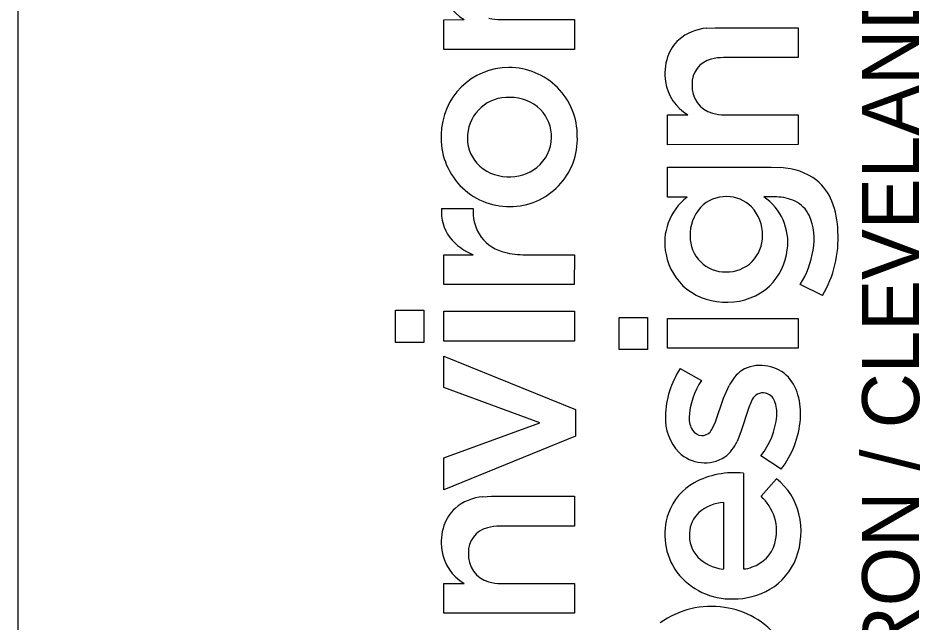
# Model space of a CAD drawing. Extents: x 0 to 34, y 0 to 22.
# Drawn here: x 32 to 32.901, y 2.778 to 3.382 of the extents above; entities that cross this region are included whole.
import ezdxf

# ---------------------------------------------------------------- set-up
doc = ezdxf.new("R2010")
doc.units = 0
doc.layers.add('SH_Border', color=7, linetype='Continuous')
doc.layers.add('SH_Data', color=7, linetype='Continuous')

msp = doc.modelspace()

# ---------------------------------------------------------------- linework, layer by layer
at = {"layer": 'SH_Border'}
msp.add_line((32, 0.5), (32, 21.5), dxfattribs=at)
at = {"layer": 'SH_Data'}
for p, q in [((32.42542, 3.38066), (32.44552, 3.38071)), ((32.42542, 3.35086), (32.42542, 3.38066)), ((32.48222, 3.38071), (32.55569, 3.38071)), ((32.55569, 3.38071), (32.55571, 3.35096)), ((32.68784, 3.3722), (32.69634, 3.37266)), ((32.69634, 3.37266), (32.77916, 3.37266)), ((32.77916, 3.37266), (32.77917, 3.34287)), ((32.55571, 3.35096), (32.42542, 3.35086)), ((32.77917, 3.34287), (32.70485, 3.3428)), ((32.64888, 3.2855), (32.66897, 3.28555)), ((32.64888, 3.25569), (32.64888, 3.2855)), ((32.70568, 3.28555), (32.77915, 3.28555)), ((32.77915, 3.28555), (32.77917, 3.25579)), ((32.77917, 3.25579), (32.64888, 3.25569)), ((32.6489, 3.20336), (32.64889, 3.23322)), ((32.64889, 3.23322), (32.75236, 3.23322)), ((32.75236, 3.23322), (32.76191, 3.23285)), ((32.66836, 3.20336), (32.6489, 3.20336)), ((32.75763, 3.20356), (32.74487, 3.20361)), ((32.42299, 3.19193), (32.45454, 3.19193)), ((32.42542, 3.14577), (32.45473, 3.14579)), ((32.42542, 3.11593), (32.42542, 3.14577)), ((32.50413, 3.14581), (32.55571, 3.14573)), ((32.55571, 3.14573), (32.55565, 3.11593)), ((32.55565, 3.11593), (32.42542, 3.11593)), ((32.8036, 3.10491), (32.7812, 3.11598)), ((32.37705, 3.05818), (32.37705, 3.09026)), ((32.37705, 3.09026), (32.40543, 3.09026)), ((32.40543, 3.09026), (32.40543, 3.05818)), ((32.42542, 3.05942), (32.42542, 3.08928)), ((32.42542, 3.08928), (32.55571, 3.08928)), ((32.55571, 3.08928), (32.55571, 3.05942)), ((32.60051, 3.05111), (32.60051, 3.08319)), ((32.60051, 3.08319), (32.62889, 3.08319)), ((32.62889, 3.08319), (32.62889, 3.05111)), ((32.64888, 3.05234), (32.64888, 3.0822)), ((32.64888, 3.0822), (32.77917, 3.0822)), ((32.77917, 3.0822), (32.77917, 3.05234)), ((32.40543, 3.05818), (32.37705, 3.05818)), ((32.55571, 3.05942), (32.42542, 3.05942)), ((32.62889, 3.05111), (32.60051, 3.05111)), ((32.77917, 3.05234), (32.64888, 3.05234)), ((32.42542, 3.01327), (32.42542, 3.0446)), ((32.42542, 3.0446), (32.5567, 2.9913)), ((32.66151, 3.03207), (32.68268, 3.02025)), ((32.52117, 2.97798), (32.42542, 3.01327)), ((32.70483, 3.00258), (32.71036, 3.01526)), ((32.69675, 2.97868), (32.70483, 3.00258)), ((32.73342, 3.00101), (32.72985, 2.9933)), ((32.5567, 2.9913), (32.5567, 2.96441)), ((32.72985, 2.9933), (32.72213, 2.96882)), ((32.42542, 2.94294), (32.52117, 2.97798)), ((32.69299, 2.97117), (32.69675, 2.97868)), ((32.5567, 2.96441), (32.42542, 2.91086)), ((32.72213, 2.96882), (32.71822, 2.95921)), ((32.42542, 2.91086), (32.42542, 2.94294)), ((32.76214, 2.93141), (32.74198, 2.94469)), ((32.72453, 2.92747), (32.72463, 2.83195)), ((32.74228, 2.90465), (32.75768, 2.922)), ((32.46439, 2.90397), (32.47289, 2.90443)), ((32.47289, 2.90443), (32.55571, 2.90443)), ((32.55571, 2.90443), (32.55571, 2.87465)), ((32.70489, 2.83182), (32.70489, 2.89834)), ((32.55571, 2.87465), (32.4814, 2.87457)), ((32.70361, 2.83165), (32.70489, 2.83182)), ((32.42542, 2.81728), (32.44552, 2.81733)), ((32.42542, 2.78747), (32.42542, 2.81728)), ((32.48222, 2.81733), (32.55569, 2.81733)), ((32.55569, 2.81733), (32.55571, 2.78756)), ((32.55571, 2.78756), (32.42542, 2.78747))]:
    msp.add_line(p, q, dxfattribs=at)
for points in [[(32.42542, 3.35086), (32.42542, 3.38066), (32.44552, 3.38071)], [(32.48222, 3.38071), (32.55569, 3.38071), (32.55571, 3.35096), (32.42542, 3.35086)], [(32.68784, 3.3722), (32.69634, 3.37266), (32.77916, 3.37266), (32.77917, 3.34287), (32.70485, 3.3428)], [(32.64888, 3.25569), (32.64888, 3.2855), (32.66897, 3.28555)], [(32.70568, 3.28555), (32.77915, 3.28555), (32.77917, 3.25579), (32.64888, 3.25569)], [(32.66836, 3.20336), (32.6489, 3.20336), (32.64889, 3.23322), (32.75236, 3.23322), (32.76191, 3.23285)], [(32.75763, 3.20356), (32.74487, 3.20361)], [(32.42299, 3.19193), (32.45454, 3.19193)], [(32.50413, 3.14581), (32.55571, 3.14573), (32.55565, 3.11593), (32.42542, 3.11593)], [(32.42542, 3.11593), (32.42542, 3.14577), (32.45473, 3.14579)], [(32.8036, 3.10491), (32.7812, 3.11598)], [(32.66151, 3.03207), (32.68268, 3.02025)], [(32.69299, 2.97117), (32.69675, 2.97868), (32.70483, 3.00258), (32.71036, 3.01526)], [(32.73342, 3.00101), (32.72985, 2.9933), (32.72213, 2.96882), (32.71822, 2.95921)], [(32.76214, 2.93141), (32.74198, 2.94469)], [(32.72453, 2.92747), (32.72463, 2.83195)], [(32.74228, 2.90465), (32.75768, 2.922)], [(32.46439, 2.90397), (32.47289, 2.90443), (32.55571, 2.90443), (32.55571, 2.87465), (32.4814, 2.87457)], [(32.70361, 2.83165), (32.70489, 2.83182), (32.70489, 2.89834)], [(32.42542, 2.78747), (32.42542, 2.81728), (32.44552, 2.81733)], [(32.48222, 2.81733), (32.55569, 2.81733), (32.55571, 2.78756), (32.42542, 2.78747)]]:
    msp.add_lwpolyline(points, dxfattribs=at)
for points in [[(32.37705, 3.05818), (32.37705, 3.09026), (32.40543, 3.09026), (32.40543, 3.05818)], [(32.42542, 3.05942), (32.42542, 3.08928), (32.55571, 3.08928), (32.55571, 3.05942)], [(32.60051, 3.05111), (32.60051, 3.08319), (32.62889, 3.08319), (32.62889, 3.05111)], [(32.64888, 3.05234), (32.64888, 3.0822), (32.77917, 3.0822), (32.77917, 3.05234)], [(32.42542, 2.91086), (32.42542, 2.94294), (32.52117, 2.97798), (32.42542, 3.01327), (32.42542, 3.0446), (32.5567, 2.9913), (32.5567, 2.96441)]]:
    msp.add_lwpolyline(points, close=True, dxfattribs=at)
for centre, radius, start, end in [((32.47027, 3.42141), 0.04763, 188.96462, 238.69865), ((32.47027, 3.42141), 0.04763, 188.96462, 238.69865), ((32.48183, 3.42286), 0.04215, 254.08913, 270.52838), ((32.48183, 3.42286), 0.04215, 254.08913, 270.52838), ((32.69216, 3.32251), 0.04988, 94.97056, 130.22484), ((32.69216, 3.32251), 0.04988, 94.97056, 130.22484), ((32.68694, 3.33085), 0.04016, 132.22383, 161.68229), ((32.68694, 3.33085), 0.04016, 132.22383, 161.68229), ((32.70217, 3.32642), 0.05602, 162.27398, 187.79173), ((32.70217, 3.32642), 0.05602, 162.27398, 187.79173), ((32.70453, 3.29679), 0.04601, 89.60515, 105.33026), ((32.70453, 3.29679), 0.04601, 89.60515, 105.33026), ((32.69828, 3.31689), 0.02498, 103.68683, 182.21395), ((32.69828, 3.31689), 0.02498, 103.68683, 182.21395), ((32.49014, 3.26543), 0.0674, 89.84756, 179.64047), ((32.49014, 3.26543), 0.0674, 89.84756, 179.64047), ((32.49057, 3.26474), 0.0681, 359.54009, 90.21138), ((32.49057, 3.26474), 0.0681, 359.54009, 90.21138), ((32.69372, 3.32624), 0.04763, 188.96462, 238.69865), ((32.69372, 3.32624), 0.04763, 188.96462, 238.69865), ((32.7008, 3.31381), 0.02757, 175.58441, 255.13816), ((32.7008, 3.31381), 0.02757, 175.58441, 255.13816), ((32.48923, 3.26263), 0.0404, 87.04809, 175.57259), ((32.48923, 3.26263), 0.0404, 87.04809, 175.57259), ((32.49204, 3.25999), 0.04299, 45.84264, 90.98008), ((32.49204, 3.25999), 0.04299, 45.84264, 90.98008), ((32.49458, 3.26421), 0.03821, 357.88569, 44.15902), ((32.49458, 3.26421), 0.03821, 357.88569, 44.15902), ((32.70529, 3.32769), 0.04215, 254.08913, 270.52838), ((32.70529, 3.32769), 0.04215, 254.08913, 270.52838), ((32.49083, 3.26209), 0.06819, 176.8344, 270.40384), ((32.49083, 3.26209), 0.06819, 176.8344, 270.40384), ((32.48729, 3.2625), 0.03848, 175.15378, 221.14706), ((32.48729, 3.2625), 0.03848, 175.15378, 221.14706), ((32.49123, 3.26139), 0.06749, 270.06243, 2.37759), ((32.49123, 3.26139), 0.06749, 270.06243, 2.37759), ((32.49446, 3.26318), 0.0383, 308.28936, 359.43468), ((32.49446, 3.26318), 0.0383, 308.28936, 359.43468), ((32.48919, 3.26607), 0.04228, 223.09994, 268.80895), ((32.48919, 3.26607), 0.04228, 223.09994, 268.80895), ((32.49096, 3.2679), 0.04418, 266.56515, 308.06078), ((32.49096, 3.2679), 0.04418, 266.56515, 308.06078), ((32.75907, 3.16789), 0.06503, 53.40344, 87.49062), ((32.75907, 3.16789), 0.06503, 53.40344, 87.49062), ((32.76517, 3.18039), 0.05141, 21.60748, 50.5577), ((32.76517, 3.18039), 0.05141, 21.60748, 50.5577), ((32.70292, 3.15813), 0.05692, 127.37482, 192.22468), ((32.70292, 3.15813), 0.05692, 127.37482, 192.22468), ((32.70693, 3.16927), 0.0346, 88.47302, 136.42562), ((32.70693, 3.16927), 0.0346, 88.47302, 136.42562), ((32.70814, 3.16963), 0.03424, 44.27195, 90.47623), ((32.70814, 3.16963), 0.03424, 44.27195, 90.47623), ((32.71421, 3.15829), 0.05472, 352.1125, 55.92295), ((32.71421, 3.15829), 0.05472, 352.1125, 55.92295), ((32.75666, 3.15725), 0.04633, 65.01687, 88.8011), ((32.75666, 3.15725), 0.04633, 65.01687, 88.8011), ((32.7626, 3.17155), 0.03085, 26.26808, 63.80301), ((32.7626, 3.17155), 0.03085, 26.26808, 63.80301), ((32.73069, 3.16714), 0.08835, 1.15143, 21.3627), ((32.73069, 3.16714), 0.08835, 1.15143, 21.3627), ((32.46616, 3.18882), 0.04329, 175.87313, 216.34747), ((32.46616, 3.18882), 0.04329, 175.87313, 216.34747), ((32.50087, 3.18948), 0.04639, 176.9688, 209.60636), ((32.50087, 3.18948), 0.04639, 176.9688, 209.60636), ((32.71141, 3.16602), 0.0401, 137.46739, 182.33237), ((32.71141, 3.16602), 0.0401, 137.46739, 182.33237), ((32.70368, 3.166), 0.03996, 358.57141, 43.53765), ((32.70368, 3.166), 0.03996, 358.57141, 43.53765), ((32.73565, 3.16154), 0.05953, 349.30734, 23.43071), ((32.73565, 3.16154), 0.05953, 349.30734, 23.43071), ((32.47466, 3.19716), 0.05511, 218.09809, 248.7907), ((32.47466, 3.19716), 0.05511, 218.09809, 248.7907), ((32.49514, 3.18814), 0.04079, 211.94466, 253.2028), ((32.49514, 3.18814), 0.04079, 211.94466, 253.2028), ((32.70645, 3.1637), 0.03511, 178.88208, 271.08374), ((32.70645, 3.1637), 0.03511, 178.88208, 271.08374), ((32.70818, 3.16404), 0.03546, 268.27882, 1.55016), ((32.70818, 3.16404), 0.03546, 268.27882, 1.55016), ((32.70538, 3.16244), 0.11383, 329.6388, 3.25998), ((32.70538, 3.16244), 0.11383, 329.6388, 3.25998), ((32.50465, 3.2165), 0.07069, 252.46555, 269.57296), ((32.50465, 3.2165), 0.07069, 252.46555, 269.57296), ((32.70463, 3.15696), 0.05837, 190.75182, 231.28919), ((32.70463, 3.15696), 0.05837, 190.75182, 231.28919), ((32.70988, 3.15708), 0.05887, 313.74196, 353.8554), ((32.70988, 3.15708), 0.05887, 313.74196, 353.8554), ((32.70738, 3.16334), 0.08771, 327.31495, 351.57478), ((32.70738, 3.16334), 0.08771, 327.31495, 351.57478), ((32.70632, 3.16112), 0.06269, 232.46061, 272.59022), ((32.70632, 3.16112), 0.06269, 232.46061, 272.59022), ((32.70954, 3.15901), 0.06051, 269.6361, 312.70877), ((32.70954, 3.15901), 0.06051, 269.6361, 312.70877), ((32.73636, 2.98258), 0.08973, 146.53104, 178.7571), ((32.73636, 2.98258), 0.08973, 146.53104, 178.7571), ((32.74661, 2.99713), 0.04053, 125.51182, 153.41595), ((32.74661, 2.99713), 0.04053, 125.51182, 153.41595), ((32.7406, 3.0026), 0.03263, 80.17192, 122.51969), ((32.7406, 3.0026), 0.03263, 80.17192, 122.51969), ((32.74278, 2.99824), 0.03667, 47.79344, 84.68918), ((32.74278, 2.99824), 0.03667, 47.79344, 84.68918), ((32.74519, 2.9789), 0.07495, 146.51121, 176.91007), ((32.74519, 2.9789), 0.07495, 146.51121, 176.91007), ((32.73788, 2.9946), 0.04267, 14.9966, 46.20632), ((32.73788, 2.9946), 0.04267, 14.9966, 46.20632), ((32.74384, 2.99631), 0.01143, 76.66094, 155.7053), ((32.74384, 2.99631), 0.01143, 76.66094, 155.7053), ((32.74397, 2.99511), 0.01256, 21.5098, 78.52618), ((32.74397, 2.99511), 0.01256, 21.5098, 78.52618), ((32.71044, 2.98674), 0.07121, 355.83062, 15.39138), ((32.71044, 2.98674), 0.07121, 355.83062, 15.39138), ((32.72592, 2.98766), 0.03209, 354.57264, 22.06805), ((32.72592, 2.98766), 0.03209, 354.57264, 22.06805), ((32.69666, 2.98238), 0.05005, 177.53659, 222.79318), ((32.69666, 2.98238), 0.05005, 177.53659, 222.79318), ((32.6931, 2.98233), 0.02276, 178.47474, 211.08679), ((32.6931, 2.98233), 0.02276, 178.47474, 211.08679), ((32.68248, 2.99149), 0.0757, 321.81101, 354.79685), ((32.68248, 2.99149), 0.0757, 321.81101, 354.79685), ((32.68952, 2.9882), 0.09219, 321.9777, 355.87384), ((32.68952, 2.9882), 0.09219, 321.9777, 355.87384), ((32.68331, 2.9767), 0.01148, 212.23676, 268.37769), ((32.68331, 2.9767), 0.01148, 212.23676, 268.37769), ((32.68342, 2.97589), 0.01067, 267.71603, 333.73375), ((32.68342, 2.97589), 0.01067, 267.71603, 333.73375), ((32.68098, 2.9758), 0.04077, 308.08772, 335.98736), ((32.68098, 2.9758), 0.04077, 308.08772, 335.98736), ((32.68599, 2.97535), 0.0375, 225.98539, 302.47965), ((32.68599, 2.97535), 0.0375, 225.98539, 302.47965), ((32.7152, 2.84414), 0.08384, 83.61499, 118.28755), ((32.7152, 2.84414), 0.08384, 83.61499, 118.28755), ((32.71744, 2.87167), 0.06443, 13.53365, 51.36148), ((32.71744, 2.87167), 0.06443, 13.53365, 51.36148), ((32.70239, 2.86906), 0.05583, 118.83082, 160.62438), ((32.70239, 2.86906), 0.05583, 118.83082, 160.62438), ((32.46871, 2.85428), 0.04988, 94.96958, 130.22249), ((32.46871, 2.85428), 0.04988, 94.96958, 130.22249), ((32.70378, 2.86556), 0.05486, 19.03571, 45.44059), ((32.70378, 2.86556), 0.05486, 19.03571, 45.44059), ((32.46348, 2.86263), 0.04015, 132.22192, 161.68183), ((32.46348, 2.86263), 0.04015, 132.22192, 161.68183), ((32.70785, 2.85609), 0.04235, 94.00805, 130.88169), ((32.70785, 2.85609), 0.04235, 94.00805, 130.88169), ((32.71041, 2.86612), 0.06437, 160.52012, 215.78311), ((32.71041, 2.86612), 0.06437, 160.52012, 215.78311), ((32.70048, 2.86628), 0.02985, 132.98507, 177.179), ((32.70048, 2.86628), 0.02985, 132.98507, 177.179), ((32.71069, 2.8697), 0.047, 344.60586, 17.007), ((32.71069, 2.8697), 0.047, 344.60586, 17.007), ((32.70635, 2.86921), 0.07579, 339.3542, 13.37853), ((32.70635, 2.86921), 0.07579, 339.3542, 13.37853), ((32.47872, 2.85819), 0.05601, 162.27355, 187.79185), ((32.47872, 2.85819), 0.05601, 162.27355, 187.79185), ((32.48108, 2.82856), 0.04601, 89.60494, 105.3284), ((32.48108, 2.82856), 0.04601, 89.60494, 105.3284), ((32.47482, 2.84867), 0.02498, 103.68646, 182.21874), ((32.47482, 2.84867), 0.02498, 103.68646, 182.21874), ((32.7017, 2.86503), 0.03115, 175.00126, 223.28301), ((32.7017, 2.86503), 0.03115, 175.00126, 223.28301), ((32.7224, 2.86715), 0.03504, 288.00773, 343.55078), ((32.7224, 2.86715), 0.03504, 288.00773, 343.55078), ((32.47026, 2.85802), 0.04762, 188.96199, 238.70369), ((32.47026, 2.85802), 0.04762, 188.96199, 238.70369), ((32.47735, 2.84558), 0.02756, 175.58538, 255.14386), ((32.47735, 2.84558), 0.02756, 175.58538, 255.14386), ((32.70891, 2.87363), 0.04231, 225.06188, 262.79738), ((32.70891, 2.87363), 0.04231, 225.06188, 262.79738), ((32.71894, 2.8652), 0.0626, 300.94269, 338.73225), ((32.71894, 2.8652), 0.0626, 300.94269, 338.73225), ((32.72474, 2.85216), 0.02021, 269.7003, 294.8711), ((32.72474, 2.85216), 0.02021, 269.7003, 294.8711), ((32.71253, 2.87054), 0.06872, 217.74516, 271.65431), ((32.71253, 2.87054), 0.06872, 217.74516, 271.65431), ((32.48183, 2.85948), 0.04215, 254.09162, 270.52835), ((32.48183, 2.85948), 0.04215, 254.09162, 270.52835), ((32.71549, 2.87241), 0.07056, 269.20477, 300.33412), ((32.71549, 2.87241), 0.07056, 269.20477, 300.33412), ((32.69229, 2.70792), 0.08641, 81.19402, 125.99844), ((32.69229, 2.70792), 0.08641, 81.19402, 125.99844), ((32.69458, 2.71132), 0.08272, 37.85208, 82.40204), ((32.69458, 2.71132), 0.08272, 37.85208, 82.40204)]:
    msp.add_arc(centre, radius, start, end, dxfattribs=at)

# ---------------------------------------------------------------- texts
msp.add_text('AKRON / CLEVELAND / COLUMBUS', height=0.056969, rotation=90, dxfattribs=at).set_placement((32.90012, 2.638))

doc.saveas('drawing.dxf')
